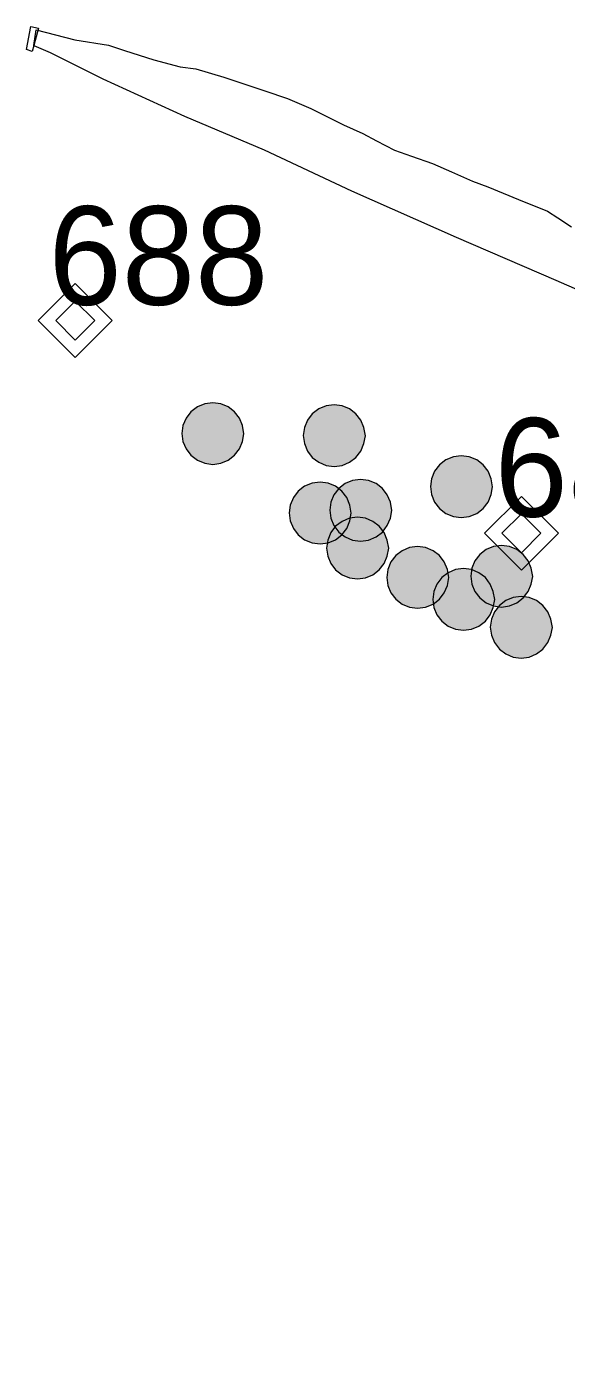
# Model space of a CAD drawing. Extents: x 3461750 to 3585707, y 5917729 to 5985917.
# Drawn here: x 3517681 to 3518777, y 5968997 to 5971685 of the extents above; entities that cross this region are included whole.
import ezdxf

# ---------------------------------------------------------------- set-up
doc = ezdxf.new("R2010")
doc.units = 0
doc.header["$LTSCALE"] = 80
for name, color, linetype, lineweight in [('15', 7, 'Continuous', 13), ('3', 7, 'Continuous', 13), ('6', 7, 'Continuous', 13), ('7', 7, 'Continuous', 13)]:
    doc.layers.add(name, color=color, linetype=linetype, lineweight=lineweight)

msp = doc.modelspace()

# ---------------------------------------------------------------- hatches: boundary and pattern name
at = {"layer": '3'}
for points in [[(3518122.21, 5970857.97), (3518119.28, 5970874.59), (3518113.03, 5970889.69), (3518103.09, 5970902.65), (3518090.13, 5970912.59), (3518075.03, 5970918.84), (3518058.84, 5970920.97), (3518042.64, 5970918.84), (3518027.55, 5970912.59), (3518014.59, 5970902.65), (3518004.65, 5970889.69), (3517998.4, 5970874.59), (3517996.26, 5970858.4), (3517998.4, 5970842.2), (3518004.65, 5970827.11), (3518014.59, 5970814.15), (3518027.55, 5970804.21), (3518042.64, 5970797.96), (3518058.84, 5970795.82), (3518075.03, 5970797.96), (3518090.13, 5970804.21), (3518103.09, 5970814.15), (3518113.03, 5970827.11), (3518119.28, 5970842.2)], [(3518368.6, 5970853.67), (3518365.67, 5970870.3), (3518359.42, 5970885.39), (3518349.47, 5970898.35), (3518336.51, 5970908.29), (3518321.42, 5970914.54), (3518305.22, 5970916.68), (3518289.03, 5970914.54), (3518273.94, 5970908.29), (3518260.98, 5970898.35), (3518251.03, 5970885.39), (3518244.78, 5970870.3), (3518242.65, 5970854.1), (3518244.78, 5970837.91), (3518251.03, 5970822.81), (3518260.98, 5970809.85), (3518273.94, 5970799.91), (3518289.03, 5970793.66), (3518305.22, 5970791.53), (3518321.42, 5970793.66), (3518336.51, 5970799.91), (3518349.47, 5970809.85), (3518359.42, 5970822.81), (3518365.67, 5970837.91)], [(3518626.8, 5970750.06), (3518623.87, 5970766.68), (3518617.62, 5970781.78), (3518607.68, 5970794.74), (3518594.72, 5970804.68), (3518579.62, 5970810.93), (3518563.43, 5970813.06), (3518547.23, 5970810.93), (3518532.14, 5970804.68), (3518519.18, 5970794.74), (3518509.24, 5970781.78), (3518502.99, 5970766.68), (3518500.85, 5970750.49), (3518502.99, 5970734.29), (3518509.24, 5970719.2), (3518519.18, 5970706.24), (3518532.14, 5970696.3), (3518547.23, 5970690.05), (3518563.43, 5970687.91), (3518579.62, 5970690.05), (3518594.72, 5970696.3), (3518607.68, 5970706.24), (3518617.62, 5970719.2), (3518623.87, 5970734.29)], [(3518340.03, 5970696.64), (3518337.1, 5970713.27), (3518330.85, 5970728.36), (3518320.91, 5970741.32), (3518307.95, 5970751.26), (3518292.86, 5970757.51), (3518276.66, 5970759.65), (3518260.46, 5970757.51), (3518245.37, 5970751.26), (3518232.41, 5970741.32), (3518222.47, 5970728.36), (3518216.22, 5970713.27), (3518214.08, 5970697.07), (3518216.22, 5970680.87), (3518222.47, 5970665.78), (3518232.41, 5970652.82), (3518245.37, 5970642.88), (3518260.46, 5970636.63), (3518276.66, 5970634.49), (3518292.86, 5970636.63), (3518307.95, 5970642.88), (3518320.91, 5970652.82), (3518330.85, 5970665.78), (3518337.1, 5970680.87)], [(3518422.31, 5970702.21), (3518419.38, 5970718.83), (3518413.13, 5970733.92), (3518403.18, 5970746.88), (3518390.22, 5970756.83), (3518375.13, 5970763.08), (3518358.94, 5970765.21), (3518342.74, 5970763.08), (3518327.65, 5970756.83), (3518314.69, 5970746.88), (3518304.74, 5970733.92), (3518298.49, 5970718.83), (3518296.36, 5970702.64), (3518298.49, 5970686.44), (3518304.74, 5970671.35), (3518314.69, 5970658.39), (3518327.65, 5970648.45), (3518342.74, 5970642.19), (3518358.94, 5970640.06), (3518375.13, 5970642.19), (3518390.22, 5970648.45), (3518403.18, 5970658.39), (3518413.13, 5970671.35), (3518419.38, 5970686.44)], [(3518415.96, 5970625.45), (3518413.03, 5970642.07), (3518406.78, 5970657.17), (3518396.84, 5970670.13), (3518383.88, 5970680.07), (3518368.78, 5970686.32), (3518352.59, 5970688.45), (3518336.39, 5970686.32), (3518321.3, 5970680.07), (3518308.34, 5970670.13), (3518298.4, 5970657.17), (3518292.15, 5970642.07), (3518290.01, 5970625.88), (3518292.15, 5970609.68), (3518298.4, 5970594.59), (3518308.34, 5970581.63), (3518321.3, 5970571.69), (3518336.39, 5970565.44), (3518352.59, 5970563.3), (3518368.78, 5970565.44), (3518383.88, 5970571.69), (3518396.84, 5970581.63), (3518406.78, 5970594.59), (3518413.03, 5970609.68)], [(3518538.08, 5970565.88), (3518535.15, 5970582.5), (3518528.9, 5970597.6), (3518518.95, 5970610.56), (3518505.99, 5970620.5), (3518490.9, 5970626.75), (3518474.71, 5970628.88), (3518458.51, 5970626.75), (3518443.42, 5970620.5), (3518430.46, 5970610.56), (3518420.52, 5970597.6), (3518414.26, 5970582.5), (3518412.13, 5970566.31), (3518414.26, 5970550.11), (3518420.52, 5970535.02), (3518430.46, 5970522.06), (3518443.42, 5970512.12), (3518458.51, 5970505.87), (3518474.71, 5970503.73), (3518490.9, 5970505.87), (3518505.99, 5970512.12), (3518518.95, 5970522.06), (3518528.9, 5970535.02), (3518535.15, 5970550.11)], [(3518708.34, 5970568.32), (3518705.41, 5970584.95), (3518699.16, 5970600.04), (3518689.22, 5970613), (3518676.26, 5970622.94), (3518661.17, 5970629.19), (3518644.97, 5970631.33), (3518628.78, 5970629.19), (3518613.68, 5970622.94), (3518600.72, 5970613), (3518590.78, 5970600.04), (3518584.53, 5970584.95), (3518582.4, 5970568.75), (3518584.53, 5970552.55), (3518590.78, 5970537.46), (3518600.72, 5970524.5), (3518613.68, 5970514.56), (3518628.78, 5970508.31), (3518644.97, 5970506.17), (3518661.17, 5970508.31), (3518676.26, 5970514.56), (3518689.22, 5970524.5), (3518699.16, 5970537.46), (3518705.41, 5970552.55)], [(3518631.29, 5970521.15), (3518628.36, 5970537.78), (3518622.11, 5970552.87), (3518612.17, 5970565.83), (3518599.21, 5970575.77), (3518584.12, 5970582.02), (3518567.92, 5970584.16), (3518551.72, 5970582.02), (3518536.63, 5970575.77), (3518523.67, 5970565.83), (3518513.73, 5970552.87), (3518507.48, 5970537.78), (3518505.34, 5970521.58), (3518507.48, 5970505.39), (3518513.73, 5970490.29), (3518523.67, 5970477.33), (3518536.63, 5970467.39), (3518551.72, 5970461.14), (3518567.92, 5970459.01), (3518584.12, 5970461.14), (3518599.21, 5970467.39), (3518612.17, 5970477.33), (3518622.11, 5970490.29), (3518628.36, 5970505.39)], [(3518748.24, 5970464.71), (3518745.31, 5970481.33), (3518739.05, 5970496.42), (3518729.11, 5970509.38), (3518716.15, 5970519.33), (3518701.06, 5970525.58), (3518684.86, 5970527.71), (3518668.67, 5970525.58), (3518653.58, 5970519.33), (3518640.62, 5970509.38), (3518630.67, 5970496.42), (3518624.42, 5970481.33), (3518622.29, 5970465.14), (3518624.42, 5970448.94), (3518630.67, 5970433.85), (3518640.62, 5970420.89), (3518653.58, 5970410.95), (3518668.67, 5970404.69), (3518684.86, 5970402.56), (3518701.06, 5970404.69), (3518716.15, 5970410.95), (3518729.11, 5970420.89), (3518739.05, 5970433.85), (3518745.31, 5970448.94)]]:
    msp.add_hatch(color=256, dxfattribs=at).paths.add_polyline_path(points)

# ---------------------------------------------------------------- linework, layer by layer
at = {"layer": '15'}
for points in [[(3517779.77, 5971162.6), (3517704.68, 5971087.51), (3517779.77, 5971012.42), (3517854.86, 5971087.51)], [(3517779.77, 5971127.2), (3517740.08, 5971087.51), (3517779.77, 5971047.82), (3517819.46, 5971087.51)], [(3518685.34, 5970730.86), (3518610.24, 5970655.77), (3518685.34, 5970580.68), (3518760.43, 5970655.77)], [(3518685.34, 5970695.47), (3518645.64, 5970655.77), (3518685.34, 5970616.08), (3518725.03, 5970655.77)]]:
    msp.add_lwpolyline(points, close=True, dxfattribs=at)
at = {"layer": '3'}
for points in [[(3518122.21, 5970857.97), (3518119.28, 5970874.59), (3518113.03, 5970889.69), (3518103.09, 5970902.65), (3518090.13, 5970912.59), (3518075.03, 5970918.84), (3518058.84, 5970920.97), (3518042.64, 5970918.84), (3518027.55, 5970912.59), (3518014.59, 5970902.65), (3518004.65, 5970889.69), (3517998.4, 5970874.59), (3517996.26, 5970858.4), (3517998.4, 5970842.2), (3518004.65, 5970827.11), (3518014.59, 5970814.15), (3518027.55, 5970804.21), (3518042.64, 5970797.96), (3518058.84, 5970795.82), (3518075.03, 5970797.96), (3518090.13, 5970804.21), (3518103.09, 5970814.15), (3518113.03, 5970827.11), (3518119.28, 5970842.2)], [(3518368.6, 5970853.67), (3518365.67, 5970870.3), (3518359.42, 5970885.39), (3518349.47, 5970898.35), (3518336.51, 5970908.29), (3518321.42, 5970914.54), (3518305.22, 5970916.68), (3518289.03, 5970914.54), (3518273.94, 5970908.29), (3518260.98, 5970898.35), (3518251.03, 5970885.39), (3518244.78, 5970870.3), (3518242.65, 5970854.1), (3518244.78, 5970837.91), (3518251.03, 5970822.81), (3518260.98, 5970809.85), (3518273.94, 5970799.91), (3518289.03, 5970793.66), (3518305.22, 5970791.53), (3518321.42, 5970793.66), (3518336.51, 5970799.91), (3518349.47, 5970809.85), (3518359.42, 5970822.81), (3518365.67, 5970837.91)], [(3518626.8, 5970750.06), (3518623.87, 5970766.68), (3518617.62, 5970781.78), (3518607.68, 5970794.74), (3518594.72, 5970804.68), (3518579.62, 5970810.93), (3518563.43, 5970813.06), (3518547.23, 5970810.93), (3518532.14, 5970804.68), (3518519.18, 5970794.74), (3518509.24, 5970781.78), (3518502.99, 5970766.68), (3518500.85, 5970750.49), (3518502.99, 5970734.29), (3518509.24, 5970719.2), (3518519.18, 5970706.24), (3518532.14, 5970696.3), (3518547.23, 5970690.05), (3518563.43, 5970687.91), (3518579.62, 5970690.05), (3518594.72, 5970696.3), (3518607.68, 5970706.24), (3518617.62, 5970719.2), (3518623.87, 5970734.29)], [(3518340.03, 5970696.64), (3518337.1, 5970713.27), (3518330.85, 5970728.36), (3518320.91, 5970741.32), (3518307.95, 5970751.26), (3518292.86, 5970757.51), (3518276.66, 5970759.65), (3518260.46, 5970757.51), (3518245.37, 5970751.26), (3518232.41, 5970741.32), (3518222.47, 5970728.36), (3518216.22, 5970713.27), (3518214.08, 5970697.07), (3518216.22, 5970680.87), (3518222.47, 5970665.78), (3518232.41, 5970652.82), (3518245.37, 5970642.88), (3518260.46, 5970636.63), (3518276.66, 5970634.49), (3518292.86, 5970636.63), (3518307.95, 5970642.88), (3518320.91, 5970652.82), (3518330.85, 5970665.78), (3518337.1, 5970680.87)], [(3518422.31, 5970702.21), (3518419.38, 5970718.83), (3518413.13, 5970733.92), (3518403.18, 5970746.88), (3518390.22, 5970756.83), (3518375.13, 5970763.08), (3518358.94, 5970765.21), (3518342.74, 5970763.08), (3518327.65, 5970756.83), (3518314.69, 5970746.88), (3518304.74, 5970733.92), (3518298.49, 5970718.83), (3518296.36, 5970702.64), (3518298.49, 5970686.44), (3518304.74, 5970671.35), (3518314.69, 5970658.39), (3518327.65, 5970648.45), (3518342.74, 5970642.19), (3518358.94, 5970640.06), (3518375.13, 5970642.19), (3518390.22, 5970648.45), (3518403.18, 5970658.39), (3518413.13, 5970671.35), (3518419.38, 5970686.44)], [(3518415.96, 5970625.45), (3518413.03, 5970642.07), (3518406.78, 5970657.17), (3518396.84, 5970670.13), (3518383.88, 5970680.07), (3518368.78, 5970686.32), (3518352.59, 5970688.45), (3518336.39, 5970686.32), (3518321.3, 5970680.07), (3518308.34, 5970670.13), (3518298.4, 5970657.17), (3518292.15, 5970642.07), (3518290.01, 5970625.88), (3518292.15, 5970609.68), (3518298.4, 5970594.59), (3518308.34, 5970581.63), (3518321.3, 5970571.69), (3518336.39, 5970565.44), (3518352.59, 5970563.3), (3518368.78, 5970565.44), (3518383.88, 5970571.69), (3518396.84, 5970581.63), (3518406.78, 5970594.59), (3518413.03, 5970609.68)], [(3518538.08, 5970565.88), (3518535.15, 5970582.5), (3518528.9, 5970597.6), (3518518.95, 5970610.56), (3518505.99, 5970620.5), (3518490.9, 5970626.75), (3518474.71, 5970628.88), (3518458.51, 5970626.75), (3518443.42, 5970620.5), (3518430.46, 5970610.56), (3518420.52, 5970597.6), (3518414.26, 5970582.5), (3518412.13, 5970566.31), (3518414.26, 5970550.11), (3518420.52, 5970535.02), (3518430.46, 5970522.06), (3518443.42, 5970512.12), (3518458.51, 5970505.87), (3518474.71, 5970503.73), (3518490.9, 5970505.87), (3518505.99, 5970512.12), (3518518.95, 5970522.06), (3518528.9, 5970535.02), (3518535.15, 5970550.11)], [(3518708.34, 5970568.32), (3518705.41, 5970584.95), (3518699.16, 5970600.04), (3518689.22, 5970613), (3518676.26, 5970622.94), (3518661.17, 5970629.19), (3518644.97, 5970631.33), (3518628.78, 5970629.19), (3518613.68, 5970622.94), (3518600.72, 5970613), (3518590.78, 5970600.04), (3518584.53, 5970584.95), (3518582.4, 5970568.75), (3518584.53, 5970552.55), (3518590.78, 5970537.46), (3518600.72, 5970524.5), (3518613.68, 5970514.56), (3518628.78, 5970508.31), (3518644.97, 5970506.17), (3518661.17, 5970508.31), (3518676.26, 5970514.56), (3518689.22, 5970524.5), (3518699.16, 5970537.46), (3518705.41, 5970552.55)], [(3518631.29, 5970521.15), (3518628.36, 5970537.78), (3518622.11, 5970552.87), (3518612.17, 5970565.83), (3518599.21, 5970575.77), (3518584.12, 5970582.02), (3518567.92, 5970584.16), (3518551.72, 5970582.02), (3518536.63, 5970575.77), (3518523.67, 5970565.83), (3518513.73, 5970552.87), (3518507.48, 5970537.78), (3518505.34, 5970521.58), (3518507.48, 5970505.39), (3518513.73, 5970490.29), (3518523.67, 5970477.33), (3518536.63, 5970467.39), (3518551.72, 5970461.14), (3518567.92, 5970459.01), (3518584.12, 5970461.14), (3518599.21, 5970467.39), (3518612.17, 5970477.33), (3518622.11, 5970490.29), (3518628.36, 5970505.39)], [(3518748.24, 5970464.71), (3518745.31, 5970481.33), (3518739.05, 5970496.42), (3518729.11, 5970509.38), (3518716.15, 5970519.33), (3518701.06, 5970525.58), (3518684.86, 5970527.71), (3518668.67, 5970525.58), (3518653.58, 5970519.33), (3518640.62, 5970509.38), (3518630.67, 5970496.42), (3518624.42, 5970481.33), (3518622.29, 5970465.14), (3518624.42, 5970448.94), (3518630.67, 5970433.85), (3518640.62, 5970420.89), (3518653.58, 5970410.95), (3518668.67, 5970404.69), (3518684.86, 5970402.56), (3518701.06, 5970404.69), (3518716.15, 5970410.95), (3518729.11, 5970420.89), (3518739.05, 5970433.85), (3518745.31, 5970448.94)]]:
    msp.add_lwpolyline(points, close=True, dxfattribs=at)
at = {"layer": '6'}
for points in [[(3517695.53, 5971645.86), (3517700.32, 5971677.57), (3517779.07, 5971657.88), (3517847.32, 5971646.95), (3517879.97, 5971636.11), (3517939.15, 5971616.79), (3517993, 5971602.78), (3518024.8, 5971598.47), (3518081.03, 5971581.62), (3518164.86, 5971554.22), (3518210.47, 5971538.13), (3518258.06, 5971517.9), (3518288.76, 5971502.27), (3518324.29, 5971485.06), (3518363.34, 5971467.6), (3518391.44, 5971452.39), (3518427.49, 5971433.31), (3518462.34, 5971421.52), (3518504.79, 5971406.79), (3518543.28, 5971389.34), (3518586.04, 5971370.89), (3518617.16, 5971358.97), (3518679.55, 5971333.1), (3518738.25, 5971310.08), (3518759.09, 5971295.93), (3518786.94, 5971277.76)], [(3517695.53, 5971645.86), (3517728.93, 5971631.63), (3517835.9, 5971578.11), (3518001.62, 5971502.32), (3518162.94, 5971434.06), (3518340.23, 5971351.01), (3518552.91, 5971257.28), (3518755, 5971169.35), (3519000.15, 5971062.44), (3519254.97, 5970946.08), (3519521.84, 5970820.05), (3519718.05, 5970713.92), (3519913.73, 5970612.84), (3520141.41, 5970478.13), (3520403.92, 5970315.16), (3520616.77, 5970167.8), (3520826, 5970018.31), (3521044.41, 5969853.85), (3521249.21, 5969689.68), (3521446.37, 5969527.72), (3521605.97, 5969389.84), (3521777.66, 5969231.93), (3521933.88, 5969084.16), (3522032.59, 5968996.9)]]:
    msp.add_lwpolyline(points, dxfattribs=at)
at = {"layer": '7'}
for points in [[(3517695.53, 5971645.86), (3517692.43, 5971634.16), (3517680.74, 5971637.91), (3517689.79, 5971684.65)], [(3517689.79, 5971684.65), (3517704.84, 5971681.02), (3517695.53, 5971645.86)], [(3517695.53, 5971645.86), (3517728.93, 5971631.63), (3517835.9, 5971578.11), (3518001.62, 5971502.32), (3518162.94, 5971434.06), (3518340.23, 5971351.01), (3518552.91, 5971257.28), (3518755, 5971169.35), (3519000.15, 5971062.44), (3519254.97, 5970946.08), (3519521.84, 5970820.05), (3519718.05, 5970713.92), (3519913.73, 5970612.84), (3520141.41, 5970478.13), (3520403.92, 5970315.16), (3520616.77, 5970167.8), (3520826, 5970018.31)]]:
    msp.add_lwpolyline(points, dxfattribs=at)

# ---------------------------------------------------------------- texts
at = {"layer": '15'}
for s, p in [('688', (3517725.4, 5971119.7)), ('687', (3518630.9, 5970689.7))]:
    msp.add_text(s, height=200, dxfattribs=at).set_placement(p)

doc.saveas('drawing.dxf')
